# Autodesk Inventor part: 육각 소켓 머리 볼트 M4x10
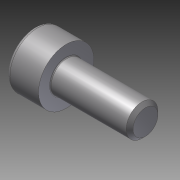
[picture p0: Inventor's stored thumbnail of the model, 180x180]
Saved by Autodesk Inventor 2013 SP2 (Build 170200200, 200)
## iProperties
Created: 2024-11
Part Number: 육각 소켓 머리 볼트 M4x10
Material: Generic
Document SubType Name: Modeling
Designer: a
Density: 1 g/cm^3
Author: a
변환 표준: STEP AP214IS
전처리기: Build: 200, Release: 2013 SP2 Update 6 - Date: Thu 07/17/2014
전송 단위: 밀리미터
불확실성: 0.01
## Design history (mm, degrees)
node "육각 소켓 머리 볼트 M4x101"
body "Solid1"
node "기준1"
